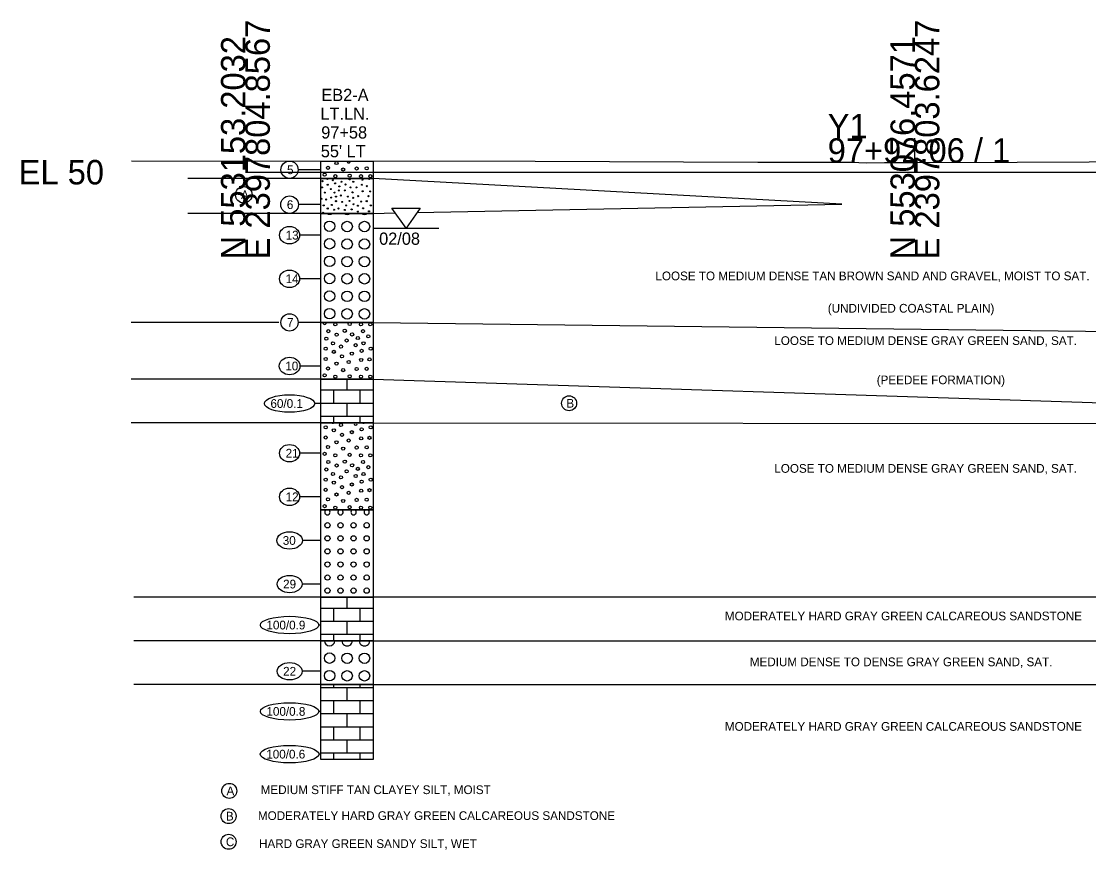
# Model space of a CAD drawing. Extents: x -26 to 164, y -74 to 517.
# Drawn here: x -25.7 to 96.7, y 422.3 to 517.3 of the extents above; entities that cross this region are included whole.
import ezdxf

# ---------------------------------------------------------------- set-up
doc = ezdxf.new("R2010")
doc.units = 0
for name, color, linetype in [('Exist XS Ground Line', 7, 'Continuous'), ('Old_Level_63', 7, 'Continuous'), ('Prop Road Sect_ Boring - Header Labels from Geopak', 7, 'Continuous'), ('Prop Road Sect_ Boring - Material (Outline)', 7, 'Continuous'), ('Prop Road Sect_ Boring - Peripheral (24 Hr GrdWtr Date)', 7, 'Continuous'), ('Prop Road Sect_ Boring - Peripheral (SPT Oval + Leader)', 7, 'Continuous'), ('Prop Road Sect_ Boring - Peripheral (SPT Tx)', 7, 'Continuous'), ('Prop Road Sect_ Material - Contact (General - Minor)', 7, 'Continuous'), ('Prop Road Sect_ Material - Tx (Composite Desc)', 7, 'Continuous'), ('Water Mark (24 Hr) Cell', 7, 'Continuous')]:
    doc.layers.add(name, color=color, linetype=linetype)

msp = doc.modelspace()

# ---------------------------------------------------------------- linework, layer by layer
at = {"layer": 'Exist XS Ground Line'}
msp.add_lwpolyline([(-13.07, 501.32), (33.21, 501.25), (58.76, 501.15), (69.47, 501.14), (71.17, 501.09), (73.28, 501.13), (73.95, 501.13), (76.76, 501.13), (88.48, 501.16), (113.22, 501.25), (157.87, 501.28)], dxfattribs=at)
at = {"layer": 'Old_Level_63'}
for p, q in [((76.76, 500), (76.76, 503.89)), ((0, 500), (76.76, 500)), ((76.76, 500), (145.76, 500))]:
    msp.add_line(p, q, dxfattribs=at)
at = {"layer": 'Prop Road Sect_ Boring - Material (Outline)'}
for p, q in [((11.65, 475.03), (11.65, 476.28)), ((8.66, 475.03), (14.65, 475.03)), ((10.15, 473.53), (10.15, 475.03)), ((13.15, 473.53), (13.15, 475.03)), ((14.65, 475.03), (14.66, 475.03)), ((8.66, 473.53), (14.65, 473.53)), ((11.65, 472.03), (11.65, 473.53)), ((14.65, 473.53), (14.66, 473.53)), ((8.66, 472.03), (14.65, 472.03)), ((10.15, 471.28), (10.15, 472.03)), ((13.15, 471.28), (13.15, 472.03)), ((14.65, 472.03), (14.66, 472.03)), ((11.65, 450.03), (11.65, 451.28)), ((8.66, 450.03), (14.65, 450.03)), ((10.15, 448.53), (10.15, 450.03)), ((13.15, 448.53), (13.15, 450.03)), ((14.65, 450.03), (14.66, 450.03)), ((8.66, 448.53), (14.65, 448.53)), ((11.65, 447.03), (11.65, 448.53)), ((14.65, 448.53), (14.66, 448.53)), ((8.66, 447.03), (14.65, 447.03)), ((10.15, 446.28), (10.15, 447.03)), ((13.15, 446.28), (13.15, 447.03)), ((14.65, 447.03), (14.66, 447.03)), ((8.66, 440.93), (14.65, 440.93)), ((10.15, 440.93), (10.15, 441.28)), ((11.65, 439.43), (11.65, 440.93)), ((13.15, 440.93), (13.15, 441.28)), ((14.65, 440.93), (14.66, 440.93)), ((8.66, 439.43), (14.65, 439.43)), ((10.15, 438.68), (10.15, 439.43)), ((13.15, 438.68), (13.15, 439.43)), ((14.65, 439.43), (14.66, 439.43)), ((10.15, 437.93), (10.15, 438.68)), ((13.15, 437.93), (13.15, 438.68)), ((8.66, 437.93), (14.65, 437.93)), ((11.65, 436.43), (11.65, 437.93)), ((14.65, 437.93), (14.66, 437.93)), ((8.66, 436.43), (14.65, 436.43)), ((10.15, 434.93), (10.15, 436.43)), ((13.15, 434.93), (13.15, 436.43)), ((14.65, 436.43), (14.66, 436.43)), ((8.66, 434.93), (14.65, 434.93)), ((11.65, 433.43), (11.65, 434.93)), ((14.65, 434.93), (14.66, 434.93)), ((8.66, 433.43), (14.65, 433.43)), ((10.15, 432.68), (10.15, 433.43)), ((13.15, 432.68), (13.15, 433.43)), ((14.65, 433.43), (14.66, 433.43))]:
    msp.add_line(p, q, dxfattribs=at)
for points in [[(8.66, 501.28), (14.66, 501.28), (14.66, 499.28), (8.66, 499.28)], [(8.66, 499.28), (14.66, 499.28), (14.66, 495.28), (8.66, 495.28)], [(8.66, 495.28), (14.66, 495.28), (14.66, 482.78), (8.66, 482.78)], [(8.66, 482.78), (14.66, 482.78), (14.66, 476.28), (8.66, 476.28)], [(8.66, 476.28), (14.66, 476.28), (14.66, 471.28), (8.66, 471.28)], [(8.66, 471.28), (14.66, 471.28), (14.66, 461.28), (8.66, 461.28)], [(8.66, 461.28), (14.66, 461.28), (14.66, 451.28), (8.66, 451.28)], [(8.66, 451.28), (14.66, 451.28), (14.66, 446.28), (8.66, 446.28)], [(8.66, 446.28), (14.66, 446.28), (14.66, 441.28), (8.66, 441.28)], [(8.66, 441.28), (14.66, 441.28), (14.66, 432.68), (8.66, 432.68)]]:
    msp.add_lwpolyline(points, close=True, dxfattribs=at)
for centre, radius in [((9.46, 500.5), 0.18), ((10.44, 501.05), 0.18), ((12.75, 500.43), 0.18), ((13.9, 500.45), 0.18), ((9.08, 499.71), 0.18), ((10.3, 499.55), 0.18), ((11.2, 500.31), 0.18), ((11.96, 499.6), 0.18), ((13.24, 499.55), 0.18), ((14.31, 499.55), 0.18), ((8.78, 498.26), 0.06), ((8.83, 498.97), 0.06), ((9.43, 498.56), 0.06), ((9.78, 498.07), 0.06), ((10.03, 499.08), 0.06), ((10.28, 498.72), 0.06), ((10.77, 498.37), 0.06), ((11.01, 498.91), 0.06), ((11.47, 498.59), 0.06), ((11.94, 499.18), 0.06), ((12.05, 498.26), 0.06), ((12.37, 498.91), 0.06), ((12.73, 498.26), 0.06), ((13.35, 498.56), 0.06), ((13.41, 499.13), 0.06), ((13.92, 498.4), 0.06), ((8.72, 496.95), 0.06), ((9.1, 497.66), 0.06), ((9.27, 496.87), 0.06), ((9.84, 497.09), 0.06), ((10.22, 497.66), 0.06), ((10.38, 497.2), 0.06), ((10.71, 497.91), 0.06), ((10.93, 497.33), 0.06), ((11.39, 497.91), 0.06), ((11.75, 497.2), 0.06), ((12.29, 497.69), 0.06), ((12.34, 497.06), 0.06), ((12.92, 497.25), 0.06), ((13.44, 497.82), 0.06), ((14.12, 497.25), 0.06), ((14.31, 497.8), 0.06), ((8.97, 496.19), 0.06), ((9.43, 495.84), 0.06), ((9.9, 496.24), 0.06), ((10.16, 495.69), 0.06), ((10.38, 496.68), 0.06), ((10.68, 495.84), 0.06), ((11.09, 496.6), 0.06), ((11.39, 495.67), 0.06), ((11.55, 496.19), 0.06), ((11.94, 496.71), 0.06), ((12.18, 495.73), 0.06), ((12.4, 496.33), 0.06), ((12.89, 496.16), 0.06), ((13.27, 496.63), 0.06), ((13.49, 495.86), 0.06), ((13.9, 496.68), 0.06), ((14.38, 496.2), 0.06), ((8.91, 495.35), 0.06), ((9.65, 493.8), 0.6), ((12.89, 495.48), 0.06), ((14.17, 495.51), 0.06), ((11.66, 493.77), 0.6), ((13.65, 493.77), 0.6), ((9.65, 491.79), 0.6), ((11.66, 491.76), 0.6), ((13.65, 491.76), 0.6), ((9.65, 489.78), 0.6), ((11.66, 489.75), 0.6), ((13.65, 489.75), 0.6), ((9.65, 487.81), 0.6), ((11.66, 487.78), 0.6), ((13.65, 487.78), 0.6), ((9.65, 485.79), 0.6), ((11.66, 485.77), 0.6), ((13.65, 485.77), 0.6), ((9.65, 483.78), 0.6), ((11.66, 483.76), 0.6), ((13.65, 483.76), 0.6), ((10.3, 482.55), 0.18), ((11.96, 482.6), 0.18), ((13.24, 482.55), 0.18), ((14.31, 482.55), 0.18), ((9.27, 480.91), 0.18), ((9.5, 481.77), 0.18), ((10.45, 481.38), 0.18), ((11.39, 481.82), 0.18), ((12.23, 481.4), 0.18), ((12.89, 480.99), 0.18), ((13.49, 481.77), 0.18), ((14.09, 481.18), 0.18), ((9.21, 479.76), 0.18), ((10.03, 480.39), 0.18), ((10.95, 480.01), 0.18), ((11.6, 480.71), 0.18), ((12.64, 480.17), 0.18), ((13.54, 480.39), 0.18), ((14.36, 479.76), 0.18), ((9.21, 478.59), 0.18), ((10.14, 479.41), 0.18), ((11.07, 478.89), 0.18), ((12.2, 479.2), 0.18), ((13.27, 478.48), 0.18), ((13.32, 479.52), 0.18), ((14.22, 478.54), 0.18), ((9.46, 477.5), 0.18), ((10.44, 478.05), 0.18), ((11.2, 477.31), 0.18), ((11.84, 478.24), 0.18), ((12.75, 477.43), 0.18), ((13.9, 477.45), 0.18), ((9.08, 476.71), 0.18), ((10.3, 476.55), 0.18), ((11.96, 476.6), 0.18), ((13.24, 476.55), 0.18), ((14.31, 476.55), 0.18), ((10.95, 471.01), 0.18), ((9.21, 470.76), 0.18), ((10.14, 470.41), 0.18), ((11.07, 469.89), 0.18), ((12.2, 470.2), 0.18), ((13.32, 470.51), 0.18), ((14.36, 470.76), 0.18), ((9.21, 469.59), 0.18), ((10.44, 469.04), 0.18), ((11.84, 469.24), 0.18), ((13.27, 469.48), 0.18), ((14.22, 469.54), 0.18), ((9.08, 467.71), 0.18), ((9.46, 468.5), 0.18), ((10.3, 467.55), 0.18), ((11.2, 468.31), 0.18), ((11.96, 467.6), 0.18), ((12.75, 468.43), 0.18), ((13.24, 467.55), 0.18), ((13.9, 468.45), 0.18), ((14.31, 467.55), 0.18), ((9.5, 466.77), 0.18), ((10.45, 466.38), 0.18), ((11.39, 466.82), 0.18), ((12.23, 466.4), 0.18), ((13.49, 466.77), 0.18), ((14.09, 466.18), 0.18), ((9.27, 465.91), 0.18), ((10.03, 465.39), 0.18), ((10.95, 465.01), 0.18), ((11.6, 465.71), 0.18), ((12.64, 465.17), 0.18), ((12.89, 465.99), 0.18), ((13.54, 465.39), 0.18), ((9.21, 464.76), 0.18), ((10.14, 464.41), 0.18), ((11.07, 463.89), 0.18), ((12.2, 464.2), 0.18), ((13.32, 464.52), 0.18), ((14.36, 464.76), 0.18), ((9.21, 463.59), 0.18), ((9.46, 462.5), 0.18), ((10.44, 463.05), 0.18), ((11.84, 463.24), 0.18), ((12.75, 462.43), 0.18), ((13.27, 463.48), 0.18), ((13.9, 462.45), 0.18), ((14.22, 463.54), 0.18), ((9.08, 461.71), 0.18), ((10.3, 461.55), 0.18), ((11.2, 462.31), 0.18), ((11.96, 461.6), 0.18), ((13.24, 461.55), 0.18), ((14.31, 461.55), 0.18), ((9.4, 459.52), 0.3), ((10.9, 459.52), 0.3), ((12.4, 459.52), 0.3), ((13.9, 459.52), 0.3), ((9.4, 458.02), 0.3), ((10.9, 458.02), 0.3), ((12.4, 458.02), 0.3), ((13.9, 458.02), 0.3), ((9.4, 456.53), 0.3), ((10.9, 456.53), 0.3), ((12.4, 456.53), 0.3), ((13.9, 456.53), 0.3), ((9.4, 455.03), 0.3), ((10.9, 455.03), 0.3), ((12.4, 455.03), 0.3), ((13.9, 455.03), 0.3), ((9.4, 453.53), 0.3), ((10.9, 453.53), 0.3), ((12.4, 453.53), 0.3), ((13.9, 453.53), 0.3), ((9.4, 452.03), 0.3), ((10.9, 452.03), 0.3), ((12.4, 452.03), 0.3), ((13.9, 452.03), 0.3), ((9.65, 444.29), 0.6), ((11.66, 444.27), 0.6), ((13.65, 444.27), 0.6), ((9.65, 442.28), 0.6), ((11.66, 442.26), 0.6), ((13.65, 442.26), 0.6)]:
    msp.add_circle(centre, radius, dxfattribs=at)
for centre, radius, start, end in [((11.84, 501.24), 0.18, 168.2251, 11.7749), ((9.4, 499.24), 0.06, 134.1492, 45.8508), ((14.2, 499.24), 0.06, 134.1492, 45.8508), ((9.65, 495.77), 0.6, 234.8946, 305.1054), ((11.66, 495.75), 0.6, 231.0865, 308.9135), ((13.65, 495.75), 0.6, 231.0865, 308.9135), ((9.08, 482.71), 0.18, 157.2061, 22.7939), ((10.03, 471.39), 0.18, 215.792, 324.208), ((12.64, 471.17), 0.18, 140.8153, 39.1847), ((13.54, 471.39), 0.18, 215.792, 324.208), ((9.4, 461.02), 0.3, 120.8079, 59.1921), ((10.9, 461.02), 0.3, 120.8079, 59.1921), ((12.4, 461.02), 0.3, 120.8079, 59.1921), ((13.9, 461.02), 0.3, 120.8079, 59.1921), ((9.65, 446.31), 0.6, 182.7567, 357.2433), ((11.66, 446.28), 0.6, 179.8909, 0.1091), ((13.65, 446.28), 0.6, 179.8909, 0.1091)]:
    msp.add_arc(centre, radius, start, end, dxfattribs=at)
at = {"layer": 'Prop Road Sect_ Boring - Peripheral (SPT Oval + Leader)'}
for p, q in [((8.66, 500.28), (6.04, 500.28)), ((8.66, 496.28), (6.06, 496.28)), ((8.66, 492.78), (6.2, 492.78)), ((8.66, 487.78), (6.2, 487.78)), ((8.66, 482.78), (6.04, 482.78)), ((8.66, 477.78), (6.24, 477.78)), ((8.66, 473.48), (7.94, 473.48)), ((8.66, 467.78), (6.2, 467.78)), ((8.66, 462.78), (6.2, 462.78)), ((8.66, 457.78), (6.53, 457.78)), ((8.66, 452.78), (6.49, 452.78)), ((8.66, 448.08), (8.4, 448.08)), ((8.66, 442.78), (6.49, 442.78)), ((8.66, 438.18), (8.4, 438.18)), ((8.66, 433.28), (8.43, 433.28))]:
    msp.add_line(p, q, dxfattribs=at)
for centre, major_axis, ratio in [((5.06, 500.28), (0, 1), 0.983465), ((5.06, 496.28), (1.01, 0), 0.992963), ((5.06, 492.78), (1.15, 0), 0.870459), ((5.06, 487.78), (1.15, 0), 0.870459), ((5.06, 482.78), (0, 1), 0.983465), ((5.06, 477.78), (1.19, 0), 0.841617), ((5.06, 473.48), (2.88, 0), 0.347089), ((5.06, 467.78), (1.15, 0), 0.870459), ((5.06, 462.78), (1.15, 0), 0.870459), ((5.06, 457.78), (1.47, 0), 0.679508), ((5.06, 452.78), (1.43, 0), 0.698186), ((5.06, 448.08), (3.35, 0), 0.298894), ((5.06, 442.78), (1.43, 0), 0.698186), ((5.06, 438.18), (3.35, 0), 0.298894), ((5.06, 433.28), (3.37, 0), 0.296798)]:
    msp.add_ellipse(centre, major_axis=major_axis, ratio=ratio, dxfattribs=at)
at = {"layer": 'Prop Road Sect_ Material - Contact (General - Minor)'}
for p, q in [((8.66, 499.28), (-6.6, 499.28)), ((8.66, 495.28), (-6.6, 495.28)), ((3.82, 482.78), (-13.09, 482.78)), ((14.66, 482.78), (138.33, 481.27)), ((8.66, 476.28), (-13.09, 476.28)), ((14.66, 476.28), (133.91, 472.4)), ((8.66, 471.28), (-13.09, 471.28)), ((14.66, 471.28), (138.33, 471.16)), ((8.66, 451.28), (-12.81, 451.28)), ((138.33, 451.27), (14.66, 451.28)), ((8.66, 446.28), (-12.81, 446.28)), ((14.66, 446.28), (138.33, 446.27)), ((8.66, 441.28), (-12.81, 441.28)), ((14.66, 441.28), (138.33, 441.27))]:
    msp.add_line(p, q, dxfattribs=at)
for points in [[(19.66, 495.38), (68.39, 496.33), (14.66, 499.28)], [(14.66, 495.28), (17.18, 495.33)]]:
    msp.add_lwpolyline(points, dxfattribs=at)
at = {"layer": 'Prop Road Sect_ Material - Tx (Composite Desc)'}
for centre, radius in [((-0.19, 497.41), 0.946), ((37.11, 473.51), 0.86), ((-1.85, 429.07), 0.86), ((-1.93, 426.17), 0.86), ((-1.93, 423.23), 0.86)]:
    msp.add_circle(centre, radius, dxfattribs=at)
at = {"layer": 'Water Mark (24 Hr) Cell'}
for p, q in [((14.66, 493.58), (18.41, 493.58)), ((18.41, 493.58), (22.16, 493.58))]:
    msp.add_line(p, q, dxfattribs=at)
msp.add_lwpolyline([(16.79, 495.89), (20.02, 495.89), (18.41, 493.58)], close=True, dxfattribs=at)

# ---------------------------------------------------------------- texts
at = {"layer": 'Old_Level_63'}
for s, p in [('E 2397804.8567', (2.8, 490)), ('E 2397803.6247', (79.56, 490)), ('N 553153.2032', (0, 490)), ('N 553076.4571', (76.76, 490))]:
    msp.add_text(s, height=2.8, rotation=90, dxfattribs=at).set_placement(p)
for s, p in [('Y1', (66.76, 503.89)), ('97+92.06 / 1', (66.76, 501.09)), ('EL 50', (-26, 498.6))]:
    msp.add_text(s, height=2.8, dxfattribs=at).set_placement(p)
at = {"layer": 'Prop Road Sect_ Boring - Header Labels from Geopak'}
for s, p in [('EB2-A', (8.71, 508.16)), ('LT.LN.', (8.6, 506.01)), ('97+58', (8.69, 503.86)), ("55' LT", (8.64, 501.71))]:
    msp.add_text(s, height=1.4, dxfattribs=at).set_placement(p)
at = {"layer": 'Prop Road Sect_ Boring - Peripheral (24 Hr GrdWtr Date)'}
msp.add_text('02/08', height=1.4, dxfattribs=at).set_placement((15.33, 491.68))
at = {"layer": 'Prop Road Sect_ Boring - Peripheral (SPT Tx)'}
for s, p in [('5', (4.77, 499.78)), ('6', (4.75, 495.78)), ('13', (4.61, 492.28)), ('14', (4.61, 487.28)), ('7', (4.77, 482.28)), ('10', (4.57, 477.28)), ('60/0.1', (2.87, 472.98)), ('21', (4.61, 467.28)), ('12', (4.61, 462.28)), ('30', (4.28, 457.28)), ('29', (4.32, 452.28)), ('100/0.9', (2.41, 447.58)), ('22', (4.32, 442.28)), ('100/0.8', (2.41, 437.68)), ('100/0.6', (2.39, 432.78))]:
    msp.add_text(s, height=1, dxfattribs=at).set_placement(p)
at = {"layer": 'Prop Road Sect_ Material - Tx (Composite Desc)'}
for s, p in [('A', (-0.51, 496.91)), ('LOOSE TO MEDIUM DENSE TAN BROWN SAND AND GRAVEL, MOIST TO SAT.', (47.01, 487.61)), ('(UNDIVIDED COASTAL PLAIN)', (66.77, 483.9)), ('LOOSE TO MEDIUM DENSE GRAY GREEN SAND, SAT.', (60.64, 480.19)), ('(PEEDEE FORMATION)', (72.38, 475.69)), ('B', (36.8, 473.01)), ('LOOSE TO MEDIUM DENSE GRAY GREEN SAND, SAT.', (60.64, 465.54)), ('MODERATELY HARD GRAY GREEN CALCAREOUS SANDSTONE', (54.97, 448.62)), ('MEDIUM DENSE TO DENSE GRAY GREEN SAND, SAT.', (57.83, 443.36)), ('MODERATELY HARD GRAY GREEN CALCAREOUS SANDSTONE', (54.97, 435.96)), ('A', (-2.17, 428.57)), ('MEDIUM STIFF TAN CLAYEY SILT, MOIST', (1.75, 428.7)), ('B', (-2.24, 425.67)), ('MODERATELY HARD GRAY GREEN CALCAREOUS SANDSTONE', (1.43, 425.73)), ('C', (-2.24, 422.73)), ('HARD GRAY GREEN SANDY SILT, WET', (1.56, 422.52))]:
    msp.add_text(s, height=1, dxfattribs=at).set_placement(p)

doc.saveas('drawing.dxf')
